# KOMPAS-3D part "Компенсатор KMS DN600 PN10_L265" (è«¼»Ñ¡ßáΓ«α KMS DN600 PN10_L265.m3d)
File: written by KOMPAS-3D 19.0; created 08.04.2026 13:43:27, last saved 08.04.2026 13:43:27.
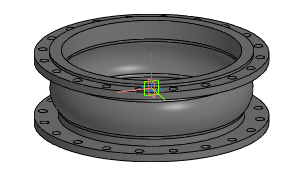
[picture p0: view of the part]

Document properties: Автор: Энергия; Полное имя файла: Z:\3.Личные\kachalov\3d для проектировщиков\7.1 Компенсатор\stp_Компенсатор KSM\Компенсатор KMS DN600 PN10_L265.m3d

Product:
- Part/product: Компенсатор KMS DN600 PN10_L265

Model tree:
1. Операция без истории:1  (labels: Компенсатор KMS DN600 PN10_L265)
